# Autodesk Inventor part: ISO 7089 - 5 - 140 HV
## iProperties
Library Location: C:\Program Files\Autodesk\Inventor 6\content
Library: local
SubLibrary: ISO
Family: 62
Member: 70
Member Major Revision: 1
Member Minor Revision: 1
Comments: To add or edit properties for Autodesk Inventor files, use iProperties.
Created: 2005-01
Part Number: ISO 7089 - 5 - 140 HV
Vendor: Autodesk Inc.
Document SubType Name: Modeling
Designer: Flavien MARTY
Description: Rondelle
Standard: ISO 7089 5 - 140 HV
Alert: To add or edit properties for Autodesk Inventor files, use iProperties.
Control State: 0
Master: False
Checked Out: False
Shininess: 64.0
Length Units: 11269
Angle Units: 11279
Time Units: 11290
Mass Units: 11283
Length Display Precision: 3
Angle Display Precision: 2
Compacted: True
Classification: un/spsc 31161807
Density: 0.0
Volumn: 0.0
Area: 0.0
PropertySet Name: Model Information
Author: Flavien MARTY
Revision Number: 1
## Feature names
1. Corps [Extrusion]
